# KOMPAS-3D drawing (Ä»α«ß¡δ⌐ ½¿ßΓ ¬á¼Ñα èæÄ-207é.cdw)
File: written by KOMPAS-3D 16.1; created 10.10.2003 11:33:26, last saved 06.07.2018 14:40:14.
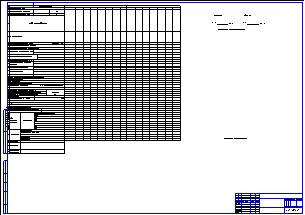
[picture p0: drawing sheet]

Sheet 1: A1, landscape

Title block, sheet 1: organisation: АО "ЧЭАЗ"; sheet format: A1; stored path: D:\Заказы\Уфа\Схема монтажа №1.cdw

Views: Вид защиты, Вид 12, Вид 13, Вид 14, Вид 1, Вид 15
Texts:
  Normal
  Body Text
  heading 1
  heading 2
  heading 3
  heading 4
  heading 5
  heading 6
  heading 7
  heading 8
  heading 9
  Body Text 2
  header
  caption
  footer
  toc 1
  toc 2
  toc 3
  toc 4
  toc 5
  toc 6
  toc 7
  toc 8
  toc 9
  Body Text Indent 2
  annotation text
  Plain Text
  Courier New
  Body Text Indent 3
  Title
  Document Map
  Tahoma
  Body Text 3
  Block Text
  ArialMT
  font5
  font6
  font7
  xl24
  xl25
  xl26
  xl27
  xl28
  xl29
  xl30
  xl31
  xl32
  xl33
  xl34
  xl35
  xl36
  xl37
  xl38
  xl39
  xl40
  xl41
  xl42
  xl43
  xl44
  xl45
  xl46
  xl47
  xl48
  xl49
  xl50
  xl51
  xl52
  xl53
  xl54
  xl55
  xl56
  xl57
  xl58
  xl59
  xl60
  xl61
  xl62
  xl63
  xl64
  xl65
  xl66
  xl67
  xl68
  xl69
  xl70
  xl71
  xl72
  xl73
  xl74
  xl75
  xl76
  xl77
  xl78
  xl79
  xl80
  xl81
  xl82
  xl83
  xl84
  xl85
  xl86
  xl87
  xl88
  xl89
  xl90
  xl91
  xl92
  xl93
  xl94
  xl95
  xl96
  xl97
  xl98
  xl99
  xl100
  xl101
  xl102
  xl103
  xl104
  xl105
  xl106
  xl107
  xl108
  xl109
  xl110
  xl111
  xl112
  xl113
  xl114
  xl115
  xl116
  xl117
  xl118
  xl119
  xl120
  xl121
  xl122
  xl123
  xl124
  xl125
  xl126
  xl127
  xl128
  xl129
  xl130
  xl131
  xl132
  xl133
  xl134
  Iniiaiie oaeno
  xl22
  xl23
  Лит-Масса-Масштаб
  Материал-Предприятие
  Title Specification
  Body Specification ( left align )
  Body Specificaton ( centered )
  textp
  ООббыыччнныыйй
  Definition Term
  Definition List
  Address
  Blockquote
  Preformatted
  z-Bottom of Form
  z-Top of Form
  № поз
  ДАННЫЕ ПО ЗАКАЗУ
  Порядковый номер камер
  Номинальное напряжение камер
  Номинальный ток сборных шин
  СХЕМА ГЛАВНЫХ ЦЕПЕЙ
  Назначение камеры
  Род тока вспомогательных цепей управления
  Номер схемы вспомогательных цепей
  Номенклатурное обозначение камеры                                   КСО-207В-___ У3
  Выключатель, тип, ток, напряжение
  Тип блока управления выключателя
  Трансформатор собственных нужд
  Трансформатор тока, тип, класс
  точности
  Трансформатор напряжения
  Тип предохранителя
  Ограничитель перенапряжения
  Тип и количество ТТ нулевой последовательности
  Трансформатор тока
  Разъединитель
  Емкостной индикатор напряжения
  Количество эл. блок-замков                          заземляющего разъединителя/в.э.
  Конечный выключатель                                      заземляющего разъединителя
  Расстояние от выключателя до нагрузки
  Устройство дуговой защиты/тип датчиков
  Измерительный преобразователь
  Тип устройства микропроцессорной защиты
  Блок питания
  Реле,
  требующие
  уточнения
  Заказчик:
  Объект:
  Проектная
  организация
  Панель оператора
  Преобразователь напряжения
  Микроконтроллерная защита
  Амперметр, А
  Вольтметр, кВ
  Данные
  для выбора
  ОПН
  Тип отходящей линии (кабельная или воздушная)
  Тип нагрузки (двигатель, трансформатор, ...)
  Тип счетчика
  Обогрев счетчиков (да/ нет)
  Количество и сечение силовых кабелей
  Тип силового кабеля
  Защита от замыкания на землю
  МТЗ
  ЗМН
  АЧР
  УРОВ
  ЛЗШ
  АВР
  ВНР
  нет
  Аппаратура
  Дополнительные технические требования
  Согласовано
  Утверждаю
  План расположения камер КСО-306
  зеленый
  желтая
  красная
  K5LT_THIN_RGB_0_0_0_THICK_0.18
  K5LT32769_RGB_0_0_0_THICK_0.18
Dimensions and other numbers on the sheet: 3 жир  расш0,75; 2; 3; 4; 5; 8; 7; 6; 9; 10; 11; 12; 13; 14; 15; 16; 17; 18; 19; 20; 21; 22; 23; 24; 25; 26; 28; 27; 29; 30; 31; 32; 33; 34; 35; 36; 37; 38; 39; 40; 42; 43; 44; 1; 41; 20__ г.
